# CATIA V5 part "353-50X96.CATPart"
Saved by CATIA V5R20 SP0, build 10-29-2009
Part number: 353-50X96
Definition: NONE
Nomenclature: 353-50X96
Source: Unknown
Description: 353-50X96
Bounding box of the stored display mesh (mm): x -10 to 86, y -32.5 to 32.5, z -32.5 to 32.5
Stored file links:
  C:\Users\Utente\Desktop\IO LAVORO\3D X SITO CF\X SITO\PLASTICA\353\353-50X96.CATPart
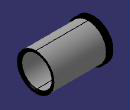
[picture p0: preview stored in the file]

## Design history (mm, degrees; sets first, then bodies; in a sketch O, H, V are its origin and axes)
Body1 "353-50X96" (main body)
  Solid1: solid without history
